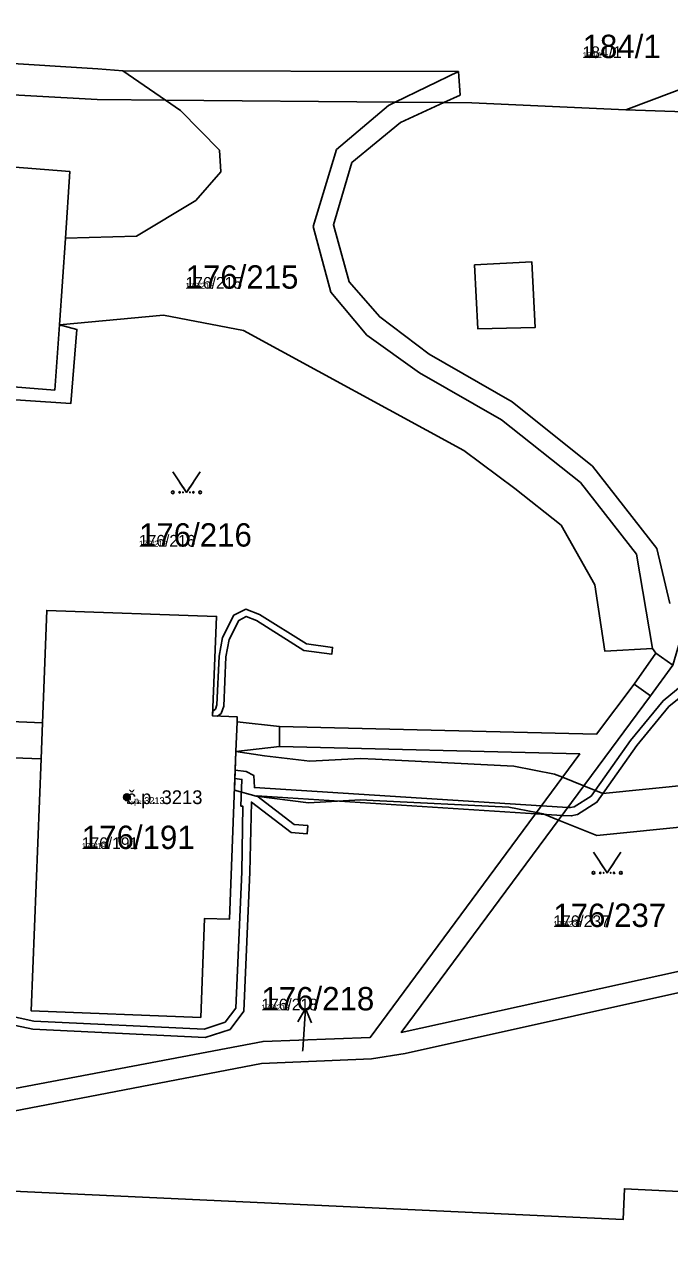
# Model space of a CAD drawing. Extents: x -759873 to -758487, y -975024 to -973516.
# Drawn here: x -759503.6 to -759456.7, y -974859.9 to -974770.4 of the extents above; entities that cross this region are included whole.
import ezdxf

# ---------------------------------------------------------------- set-up
doc = ezdxf.new("R2010")
doc.units = 0
for name, color, linetype in [('KAT_02_hranice parcel', 7, 'Continuous'), ('KAT_03_1000_st čísla parcelní', 7, 'Continuous'), ('KAT_03_1000_čísla parcelní', 7, 'Continuous'), ('KAT_03_1000_čísla popisná', 7, 'Continuous'), ('KAT_03_250_st čísla parcelní', 7, 'Continuous'), ('KAT_03_250_čísla parcelní', 7, 'Continuous'), ('KAT_03_250_čísla popisná', 7, 'Continuous'), ('KAT_03_500_st čísla parcelní', 7, 'Continuous'), ('KAT_03_500_čísla parcelní', 7, 'Continuous'), ('KAT_03_500_čísla popisná', 7, 'Continuous'), ('KAT_04_vnitřní kresba', 7, 'Continuous'), ('KAT_05_1000_značky kultur', 7, 'Continuous'), ('KAT_05_250_značky kultur', 7, 'Continuous'), ('KAT_05_500_značky kultur', 7, 'Continuous'), ('KAT_07_1000_značky budov', 7, 'Continuous'), ('KAT_07_250_značky budov', 7, 'Continuous'), ('KAT_07_500_značky budov', 7, 'Continuous'), ('KAT_10_věcná břemena', 7, 'Continuous'), ('KAT_12_pomocná šipka', 7, 'Continuous'), ('KAT_14_plocha_budovy', 7, 'Continuous'), ('KAT_14_plocha_pozemek', 7, 'Continuous')]:
    doc.layers.add(name, color=color, linetype=linetype)

msp = doc.modelspace()

# ---------------------------------------------------------------- linework, layer by layer
at = {"layer": 'KAT_02_hranice parcel'}
for p, q in [((-759501.06, -974792.24), (-759500.61, -974785.93)), ((-759457.64, -974816.15), (-759456.41, -974817.02)), ((-759485.03, -974822.94), (-759485.03, -974821.49))]:
    msp.add_line(p, q, dxfattribs=at)
for points in [[(-759432.32, -974766.17), (-759452, -974776.85), (-759459.82, -974776.57), (-759471.04, -974776.07), (-759473.09, -974776.05)], [(-759493.33, -974775.87), (-759498.32, -974775.83), (-759582.59, -974771.17), (-759622.27, -974767.52)], [(-759500.61, -974785.93), (-759500.3, -974781.07), (-759541.75, -974777.79), (-759572.8, -974775.33), (-759609.95, -974772.38), (-759610.35, -974777.27)], [(-759500.61, -974785.93), (-759495.44, -974785.77), (-759491.14, -974783.19), (-759489.31, -974781.1), (-759489.41, -974779.52), (-759492.24, -974776.63), (-759493.33, -974775.87)], [(-759473.09, -974776.05), (-759476.62, -974776.02), (-759493.33, -974775.87)], [(-759456.64, -974812.53), (-759457.57, -974808.53), (-759462.26, -974802.53), (-759468.11, -974797.84), (-759474.14, -974794.38), (-759477.74, -974791.66), (-759479.98, -974789.1), (-759481.11, -974784.96), (-759479.77, -974780.42), (-759476.24, -974777.5), (-759473.09, -974776.05)], [(-759612.26, -974788.87), (-759595.53, -974790.27), (-759574.41, -974792.12), (-759557.24, -974793.62), (-759539.2, -974795.18), (-759522.98, -974796.45), (-759500.22, -974797.96), (-759499.79, -974792.57), (-759501.06, -974792.24)], [(-759501.06, -974792.24), (-759493.49, -974791.53), (-759487.65, -974792.64), (-759471.63, -974801.39), (-759467.9, -974804.15), (-759464.54, -974806.81), (-759462.08, -974811.17), (-759461.36, -974815.99), (-759457.88, -974815.81), (-759457.64, -974816.15)], [(-759522.73, -974853.07), (-759508.22, -974850.21), (-759486.35, -974846.03), (-759478.35, -974845.69), (-759475.89, -974845.29), (-759439.14, -974837.12), (-759426.25, -974824.24), (-759419.13, -974816.38), (-759413.01, -974806.77), (-759411.92, -974804.78)], [(-759485.03, -974821.49), (-759488.12, -974821.13), (-759488.11, -974820.78), (-759489.91, -974820.71), (-759489.62, -974813.47), (-759501.98, -974813.03), (-759502.3, -974821.21), (-759506.34, -974821.05)], [(-759434.61, -974814.81), (-759420.32, -974815.53), (-759427.43, -974823.31), (-759439.96, -974835.78), (-759476.18, -974843.76), (-759458.03, -974819.25), (-759456.41, -974817.02)], [(-759485.03, -974821.49), (-759461.96, -974822.03), (-759459.23, -974818.41), (-759457.64, -974816.15)], [(-759522.64, -974851.36), (-759508.43, -974848.63), (-759486.23, -974844.41), (-759478.44, -974844.12), (-759463.18, -974823.48), (-759485.03, -974822.94)], [(-759506.45, -974823.68), (-759502.4, -974823.83), (-759503.12, -974842.18), (-759490.77, -974842.66), (-759490.49, -974835.46), (-759488.69, -974835.52), (-759488.21, -974823.29), (-759485.03, -974822.94)], [(-759443.37, -974853.62), (-759445.5, -974855.85), (-759459.93, -974855.14), (-759460.02, -974857.37), (-759508.63, -974855.12), (-759522.81, -974859.11)]]:
    msp.add_lwpolyline(points, dxfattribs=at)
at = {"layer": 'KAT_03_1000_čísla popisná'}
msp.add_circle((-759496.15, -974826.63), 0.25, dxfattribs=at)
at = {"layer": 'KAT_03_250_čísla popisná'}
msp.add_circle((-759496.15, -974826.63), 0.0625, dxfattribs=at)
at = {"layer": 'KAT_03_500_čísla popisná'}
msp.add_circle((-759496.15, -974826.63), 0.125, dxfattribs=at)
at = {"layer": 'KAT_04_vnitřní kresba'}
for p, q in [((-759582.51, -974768.44), (-759498.27, -974773.58)), ((-759498.27, -974773.58), (-759496.44, -974773.73)), ((-759496.44, -974773.73), (-759493.33, -974775.87)), ((-759496.44, -974773.73), (-759472, -974773.78)), ((-759476.62, -974776.02), (-759472, -974773.78)), ((-759472, -974773.78), (-759471.89, -974775.5)), ((-759459.82, -974776.57), (-759451.42, -974773.41)), ((-759477.11, -974776.26), (-759476.62, -974776.02)), ((-759473.09, -974776.05), (-759471.89, -974775.5)), ((-759480.89, -974779.47), (-759477.11, -974776.26)), ((-759482.58, -974785.07), (-759480.89, -974779.47)), ((-759482.58, -974785.07), (-759481.3, -974789.86)), ((-759481.3, -974789.86), (-759478.68, -974792.99)), ((-759501.39, -974797), (-759501.06, -974792.24)), ((-759478.68, -974792.99), (-759474.84, -974795.72)), ((-759539.16, -974793.84), (-759501.39, -974797)), ((-759474.84, -974795.72), (-759468.87, -974799.15)), ((-759468.87, -974799.15), (-759463.14, -974803.71)), ((-759463.14, -974803.71), (-759459.06, -974808.94)), ((-759459.06, -974808.94), (-759457.88, -974815.81)), ((-759459.23, -974818.41), (-759458.03, -974819.25)), ((-759502.4, -974823.83), (-759502.3, -974821.21)), ((-759488.21, -974823.29), (-759488.12, -974821.13))]:
    msp.add_line(p, q, dxfattribs=at)
at = {"layer": 'KAT_05_1000_značky kultur'}
for points in [[(-759492.81, -974802.929), (-759491.81, -974804.43), (-759490.81, -974802.929)], [(-759462.19, -974830.639), (-759461.19, -974832.14), (-759460.19, -974830.639)]]:
    msp.add_lwpolyline(points, dxfattribs=at)
for centre in [(-759492.81, -974804.429), (-759490.81, -974804.429), (-759462.19, -974832.139), (-759460.19, -974832.139)]:
    msp.add_circle(centre, 0.1, dxfattribs=at)
at = {"layer": 'KAT_05_250_značky kultur'}
for points in [[(-759492.06, -974804.055), (-759491.81, -974804.43), (-759491.56, -974804.055)], [(-759461.44, -974831.765), (-759461.19, -974832.14), (-759460.94, -974831.765)]]:
    msp.add_lwpolyline(points, dxfattribs=at)
for centre in [(-759492.06, -974804.43), (-759491.56, -974804.43), (-759461.44, -974832.14), (-759460.94, -974832.14)]:
    msp.add_circle(centre, 0.025, dxfattribs=at)
at = {"layer": 'KAT_05_500_značky kultur'}
for points in [[(-759492.31, -974803.679), (-759491.81, -974804.43), (-759491.31, -974803.679)], [(-759461.69, -974831.39), (-759461.19, -974832.14), (-759460.69, -974831.39)]]:
    msp.add_lwpolyline(points, dxfattribs=at)
for centre in [(-759492.31, -974804.43), (-759491.31, -974804.43), (-759461.69, -974832.14), (-759460.69, -974832.14)]:
    msp.add_circle(centre, 0.05, dxfattribs=at)
at = {"layer": 'KAT_07_1000_značky budov'}
msp.add_circle((-759496.157, -974826.629), 0.175, dxfattribs=at)
at = {"layer": 'KAT_07_250_značky budov'}
msp.add_circle((-759496.152, -974826.63), 0.0437, dxfattribs=at)
at = {"layer": 'KAT_07_500_značky budov'}
msp.add_circle((-759496.153, -974826.63), 0.0875, dxfattribs=at)
at = {"layer": 'KAT_10_věcná břemena'}
for points in [[(-759470.85, -974787.86), (-759470.6, -974792.53), (-759466.42, -974792.42), (-759466.67, -974787.65)], [(-759489.9, -974820.36), (-759489.91, -974820.71), (-759489.55, -974820.72), (-759489.28, -974820.53), (-759489.09, -974820), (-759488.94, -974816.41), (-759488.71, -974815.15), (-759487.99, -974813.75), (-759487.46, -974813.47), (-759486.72, -974813.77), (-759483.26, -974815.95), (-759481.24, -974816.22), (-759481.18, -974815.72), (-759483.08, -974815.47), (-759486.5, -974813.33), (-759487.48, -974812.93), (-759488.37, -974813.37), (-759489.19, -974814.99), (-759489.44, -974816.35), (-759489.59, -974819.9), (-759489.7, -974820.21)], [(-759452.66, -974825.8), (-759455.01, -974825.71), (-759461.5, -974826.35), (-759462.88, -974825.8), (-759464.44, -974825.18), (-759465.02, -974824.95), (-759467.99, -974824.38), (-759478.06, -974823.86), (-759479.14, -974823.81), (-759482.83, -974824.01), (-759486.13, -974823.61), (-759488.21, -974823.29), (-759488.32, -974826.11), (-759486.73, -974826.55), (-759482.93, -974827.03), (-759479.14, -974826.81), (-759478.22, -974826.86), (-759468.35, -974827.36), (-759466.34, -974827.75), (-759465.86, -974827.85), (-759464.73, -974828.3), (-759461.94, -974829.41), (-759454.93, -974828.71), (-759452.78, -974828.8)]]:
    msp.add_lwpolyline(points, close=True, dxfattribs=at)
for points in [[(-759506, -974842.89), (-759502.99, -974843.53), (-759490.45, -974844.12), (-759488.64, -974843.54), (-759487.63, -974842.2), (-759487.19, -974832.09), (-759487.09, -974826.99), (-759484.2, -974829.19), (-759483.03, -974829.3), (-759482.98, -974828.7), (-759483.98, -974828.61), (-759486.7, -974826.54), (-759466.39, -974827.83), (-759464.47, -974827.95), (-759463.8, -974827.99), (-759463.34, -974827.88), (-759461.94, -974827), (-759459.02, -974822.87), (-759456.7, -974820.02), (-759455.32, -974818.9)], [(-759455.74, -974818.46), (-759457.12, -974819.6), (-759459.5, -974822.51), (-759462.36, -974826.56), (-759463.58, -974827.32), (-759463.86, -974827.39), (-759464.05, -974827.38), (-759465.97, -974827.26), (-759486.87, -974825.93), (-759486.92, -974825.04), (-759487.46, -974824.76), (-759488.26, -974824.66), (-759488.29, -974825.26), (-759487.77, -974825.33), (-759487.85, -974827.28), (-759487.7, -974827.29), (-759487.79, -974832.07), (-759488.23, -974841.98), (-759489, -974843.02), (-759490.53, -974843.52), (-759502.91, -974842.93), (-759505.92, -974842.29)]]:
    msp.add_lwpolyline(points, dxfattribs=at)
at = {"layer": 'KAT_12_pomocná šipka'}
for p, q in [((-759483.141, -974842.026), (-759483.71, -974842.99)), ((-759483.35, -974845.02), (-759483.141, -974842.026)), ((-759483.141, -974842.026), (-759482.711, -974843.06)), ((-759483.36, -974845.13), (-759483.35, -974845.02))]:
    msp.add_line(p, q, dxfattribs=at)
at = {"layer": 'KAT_14_plocha_budovy'}
msp.add_lwpolyline([(-759490.77, -974842.66), (-759490.49, -974835.46), (-759488.69, -974835.52), (-759488.21, -974823.29), (-759488.12, -974821.13), (-759488.11, -974820.78), (-759489.91, -974820.71), (-759489.62, -974813.47), (-759501.98, -974813.03), (-759502.3, -974821.21), (-759502.4, -974823.83), (-759503.12, -974842.18)], close=True, dxfattribs=at)
at = {"layer": 'KAT_14_plocha_pozemek'}
for points in [[(-759622.27, -974767.52), (-759582.59, -974771.17), (-759498.32, -974775.83), (-759493.33, -974775.87), (-759476.62, -974776.02), (-759473.09, -974776.05), (-759471.04, -974776.07), (-759459.82, -974776.57), (-759452, -974776.85)], [(-759456.64, -974812.53), (-759457.57, -974808.53), (-759462.26, -974802.53), (-759468.11, -974797.84), (-759474.14, -974794.38), (-759477.74, -974791.66), (-759479.98, -974789.1), (-759481.11, -974784.96), (-759479.77, -974780.42), (-759476.24, -974777.5), (-759473.09, -974776.05), (-759476.62, -974776.02), (-759493.33, -974775.87), (-759492.24, -974776.63), (-759489.41, -974779.52), (-759489.31, -974781.1), (-759491.14, -974783.19), (-759495.44, -974785.77), (-759500.61, -974785.93), (-759501.06, -974792.24), (-759493.49, -974791.53), (-759487.65, -974792.64), (-759471.63, -974801.39), (-759467.9, -974804.15), (-759464.54, -974806.81), (-759462.08, -974811.17), (-759461.36, -974815.99), (-759457.88, -974815.81), (-759457.64, -974816.15), (-759456.41, -974817.02)], [(-759452, -974776.85), (-759459.82, -974776.57), (-759471.04, -974776.07), (-759473.09, -974776.05), (-759476.24, -974777.5), (-759479.77, -974780.42), (-759481.11, -974784.96), (-759479.98, -974789.1), (-759477.74, -974791.66), (-759474.14, -974794.38), (-759468.11, -974797.84), (-759462.26, -974802.53), (-759457.57, -974808.53), (-759456.64, -974812.53)], [(-759506.34, -974821.05), (-759502.3, -974821.21), (-759501.98, -974813.03), (-759489.62, -974813.47), (-759489.91, -974820.71), (-759488.11, -974820.78), (-759488.12, -974821.13), (-759485.03, -974821.49), (-759461.96, -974822.03), (-759459.23, -974818.41), (-759457.64, -974816.15), (-759457.88, -974815.81), (-759461.36, -974815.99), (-759462.08, -974811.17), (-759464.54, -974806.81), (-759467.9, -974804.15), (-759471.63, -974801.39), (-759487.65, -974792.64), (-759493.49, -974791.53), (-759501.06, -974792.24), (-759499.79, -974792.57), (-759500.22, -974797.96), (-759522.98, -974796.45)], [(-759439.96, -974835.78), (-759476.18, -974843.76), (-759458.03, -974819.25), (-759456.41, -974817.02), (-759457.64, -974816.15), (-759459.23, -974818.41), (-759461.96, -974822.03), (-759485.03, -974821.49), (-759485.03, -974822.94), (-759463.18, -974823.48), (-759478.44, -974844.12), (-759486.23, -974844.41), (-759508.43, -974848.63), (-759522.64, -974851.36), (-759522.73, -974853.07), (-759508.22, -974850.21), (-759486.35, -974846.03), (-759478.35, -974845.69), (-759475.89, -974845.29), (-759439.14, -974837.12)], [(-759439.14, -974837.12), (-759475.89, -974845.29), (-759478.35, -974845.69), (-759486.35, -974846.03), (-759508.22, -974850.21), (-759522.73, -974853.07), (-759522.78, -974853.97), (-759522.95, -974856.71), (-759523.09, -974859.11), (-759522.81, -974859.11), (-759508.63, -974855.12), (-759460.02, -974857.37), (-759459.93, -974855.14), (-759445.5, -974855.85)], [(-759445.5, -974855.85), (-759459.93, -974855.14), (-759460.02, -974857.37), (-759508.63, -974855.12), (-759522.81, -974859.11), (-759523.06, -974862.69), (-759523.84, -974879.95), (-759532.34, -974886.85), (-759531.93, -974887.1), (-759532.68, -974898.32), (-759561.57, -974897.09), (-759590.3, -974896.25), (-759598.34, -974895.81), (-759598.59, -974907.75), (-759628.97, -974906.63), (-759630.26, -974935.59)]]:
    msp.add_lwpolyline(points, dxfattribs=at)
for points in [[(-759493.33, -974775.87), (-759498.32, -974775.83), (-759582.59, -974771.17), (-759622.27, -974767.52), (-759617.87, -974768.52), (-759619.06, -974771.36), (-759617.11, -974774.92), (-759613.56, -974776.84), (-759610.35, -974777.27), (-759609.95, -974772.38), (-759572.8, -974775.33), (-759541.75, -974777.79), (-759500.3, -974781.07), (-759500.61, -974785.93), (-759495.44, -974785.77), (-759491.14, -974783.19), (-759489.31, -974781.1), (-759489.41, -974779.52), (-759492.24, -974776.63)], [(-759500.61, -974785.93), (-759500.3, -974781.07), (-759541.75, -974777.79), (-759572.8, -974775.33), (-759609.95, -974772.38), (-759610.35, -974777.27), (-759610.74, -974783.04), (-759611.74, -974782.97), (-759612.26, -974788.87), (-759595.53, -974790.27), (-759574.41, -974792.12), (-759557.24, -974793.62), (-759539.2, -974795.18), (-759522.98, -974796.45), (-759500.22, -974797.96), (-759499.79, -974792.57), (-759501.06, -974792.24)], [(-759502.4, -974823.83), (-759503.12, -974842.18), (-759490.77, -974842.66), (-759490.49, -974835.46), (-759488.69, -974835.52), (-759488.21, -974823.29), (-759485.03, -974822.94), (-759485.03, -974821.49), (-759488.12, -974821.13), (-759488.11, -974820.78), (-759489.91, -974820.71), (-759489.62, -974813.47), (-759501.98, -974813.03), (-759502.3, -974821.21), (-759506.34, -974821.05), (-759506.45, -974823.68)], [(-759434.61, -974814.81), (-759438.02, -974815.13), (-759438.52, -974827.35), (-759440.32, -974827.27), (-759440.62, -974834.53), (-759452.98, -974834.03), (-759452.24, -974814.85), (-759455.74, -974814.72), (-759456.41, -974817.02), (-759458.03, -974819.25), (-759476.18, -974843.76), (-759439.96, -974835.78), (-759427.43, -974823.31), (-759420.32, -974815.53)], [(-759486.23, -974844.41), (-759478.44, -974844.12), (-759463.18, -974823.48), (-759485.03, -974822.94), (-759488.21, -974823.29), (-759488.69, -974835.52), (-759490.49, -974835.46), (-759490.77, -974842.66), (-759503.12, -974842.18), (-759502.4, -974823.83), (-759506.45, -974823.68), (-759516.14, -974838.29), (-759522.41, -974846.1), (-759522.53, -974848.8), (-759522.64, -974851.36), (-759508.43, -974848.63)]]:
    msp.add_lwpolyline(points, close=True, dxfattribs=at)

# ---------------------------------------------------------------- texts
at = {"layer": 'KAT_03_1000_st čísla parcelní'}
msp.add_text('176/191', height=1.7, dxfattribs=at).set_placement((-759499.43, -974830.4))
at = {"layer": 'KAT_03_1000_čísla parcelní'}
for s, p in [('184/1', (-759462.98, -974772.809)), ('176/215', (-759491.88, -974789.6)), ('176/216', (-759495.27, -974808.38)), ('176/237', (-759465.11, -974836.08)), ('176/218', (-759486.36, -974842.15))]:
    msp.add_text(s, height=1.7, dxfattribs=at).set_placement(p)
at = {"layer": 'KAT_03_1000_čísla popisná'}
msp.add_text('č.p. 3213', height=1, dxfattribs=at).set_placement((-759496.15, -974827.13))
at = {"layer": 'KAT_03_250_st čísla parcelní'}
msp.add_text('176/191', height=0.425, dxfattribs=at).set_placement((-759499.43, -974830.4))
at = {"layer": 'KAT_03_250_čísla parcelní'}
for s, p in [('184/1', (-759462.98, -974772.809)), ('176/215', (-759491.88, -974789.6)), ('176/216', (-759495.27, -974808.38)), ('176/237', (-759465.11, -974836.08)), ('176/218', (-759486.36, -974842.15))]:
    msp.add_text(s, height=0.425, dxfattribs=at).set_placement(p)
at = {"layer": 'KAT_03_250_čísla popisná'}
msp.add_text('č.p. 3213', height=0.25, dxfattribs=at).set_placement((-759496.15, -974827.13))
at = {"layer": 'KAT_03_500_st čísla parcelní'}
msp.add_text('176/191', height=0.85, dxfattribs=at).set_placement((-759499.43, -974830.4))
at = {"layer": 'KAT_03_500_čísla parcelní'}
for s, p in [('184/1', (-759462.98, -974772.809)), ('176/215', (-759491.88, -974789.6)), ('176/216', (-759495.27, -974808.38)), ('176/237', (-759465.11, -974836.08)), ('176/218', (-759486.36, -974842.15))]:
    msp.add_text(s, height=0.85, dxfattribs=at).set_placement(p)
at = {"layer": 'KAT_03_500_čísla popisná'}
msp.add_text('č.p. 3213', height=0.5, dxfattribs=at).set_placement((-759496.15, -974827.13))

doc.saveas('drawing.dxf')
